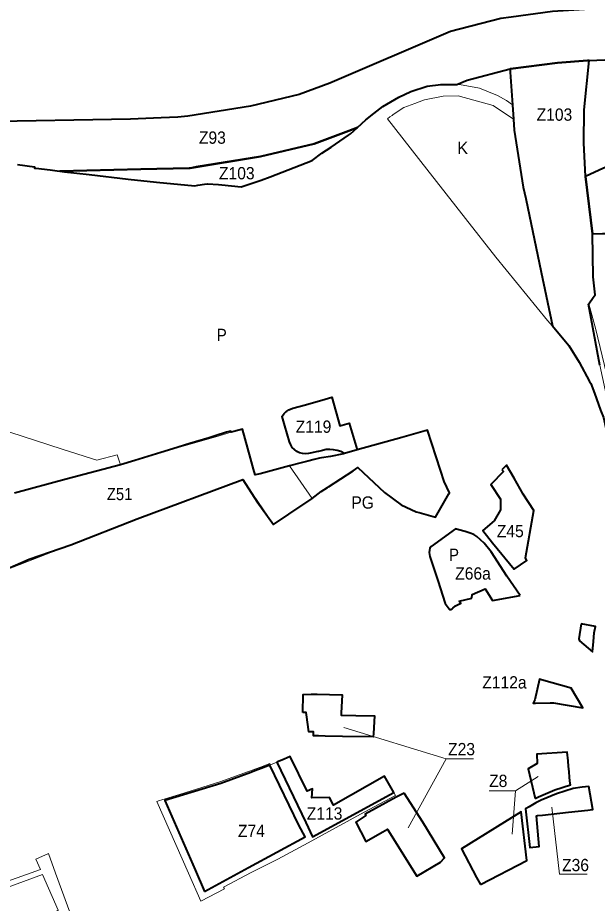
# Model space of a CAD drawing. Extents: x -650276 to -642489, y -1074311 to -1066658.
# Drawn here: x -649001 to -647871, y -1070697 to -1068970 of the extents above; entities that cross this region are included whole.
import ezdxf

# ---------------------------------------------------------------- set-up
doc = ezdxf.new("R2010")
doc.units = 0
doc.header["$LTSCALE"] = 9.6
for name, color, linetype, lineweight in [('44', 7, 'Continuous', 40), ('45', 7, 'Continuous', 40), ('46', 7, 'Continuous', 13), ('47', 7, 'Continuous', 13), ('48', 7, 'Continuous', 13), ('60', 7, 'Continuous', 35), ('63', 7, 'Continuous', 13)]:
    doc.layers.add(name, color=color, linetype=linetype, lineweight=lineweight)

msp = doc.modelspace()

# ---------------------------------------------------------------- linework, layer by layer
at = {"layer": '44'}
for points in [[(-647749.978, -1068953.416), (-647850.043, -1068951.099), (-647864.531, -1068951.823), (-647895.901, -1068953.392), (-647958.168, -1068957.73), (-648038.596, -1068968.281), (-648038.596, -1068968.281), (-648038.746, -1068968.301), (-648058.764, -1068970.927)], [(-648058.764, -1068970.927), (-648156.739, -1068996.273), (-648392.002, -1069097.554), (-648451.865, -1069119.456), (-648547.243, -1069141.81), (-648668.959, -1069161.838), (-648688.912, -1069163.603), (-648721.315, -1069164.952), (-648781.015, -1069167.44), (-649076.02, -1069172.683)], [(-647948.18, -1069057.276), (-647889.927, -1069053.218), (-647886.615, -1069053.052)], [(-647886.615, -1069053.052), (-647889.927, -1069053.218), (-647948.18, -1069057.276)], [(-647887.087, -1069527.229), (-647878.73, -1069515.45), (-647874.75, -1069509.84), (-647878.93, -1069475.09), (-647880.326, -1069390.832), (-647893.553, -1069279.021), (-647896.67, -1069213.573), (-647896.362, -1069149.171), (-647886.615, -1069053.052)], [(-647886.615, -1069053.052), (-647856.541, -1069051.548), (-647756.441, -1069053.207), (-647708.401, -1069056.275), (-647511.94, -1069076.703), (-647426.417, -1069084.624), (-647344.902, -1069091.02), (-647270.522, -1069094.255), (-647197.498, -1069094.255), (-647123.648, -1069091.043), (-647065.688, -1069087.73)], [(-648665.007, -1069262.694), (-648527.693, -1069239.938), (-648423.173, -1069215.44), (-648354.978, -1069190.492), (-648338.523, -1069183.389), (-648322.14, -1069168.56), (-648306.83, -1069156.57), (-648289.25, -1069142.79), (-648257.5, -1069124.41), (-648234.22, -1069113.6), (-648202.46, -1069103.3), (-648175.65, -1069099.64), (-648144.866, -1069099.987), (-648124.327, -1069091.181), (-648040.705, -1069069.547), (-648040.456, -1069069.483)], [(-648040.456, -1069069.483), (-648040.537, -1069075.531), (-648036.291, -1069139.458), (-648034.421, -1069167.61)], [(-648040.456, -1069069.483), (-648039.666, -1069069.279), (-647948.18, -1069057.276)], [(-647948.18, -1069057.276), (-648039.666, -1069069.279), (-648040.456, -1069069.483)], [(-648034.421, -1069167.61), (-648033, -1069189), (-648015, -1069300), (-648010.092, -1069322.087), (-647980.331, -1069465.915), (-647958.34, -1069570.699), (-647925.99, -1069608.57)], [(-648354.978, -1069190.492), (-648423.173, -1069215.44), (-648527.693, -1069239.938), (-648652.716, -1069260.657)], [(-648526.15, -1069286.21), (-648508.95, -1069280.01), (-648427.08, -1069247.75), (-648407.73, -1069233.88), (-648389.91, -1069221.86), (-648355.81, -1069198.88), (-648351.77, -1069195.88), (-648338.523, -1069183.389), (-648354.978, -1069190.492)], [(-649001.3, -1069255.92), (-648968.49, -1069260.36), (-648968.05, -1069263.06), (-648965.8, -1069262.75), (-648937.91, -1069266.51), (-648924.13, -1069268.21), (-648918.889, -1069268.875)], [(-648652.716, -1069260.657), (-648665.007, -1069262.694), (-648666.827, -1069262.738)], [(-648918.889, -1069268.875), (-648761.189, -1069265.035), (-648666.827, -1069262.738), (-648665.007, -1069262.694)], [(-648666.827, -1069262.738), (-648761.189, -1069265.035), (-648918.889, -1069268.875), (-648909.86, -1069270.02), (-648861.49, -1069275.34), (-648785.92, -1069284.2), (-648730.66, -1069290.43), (-648730.66, -1069290.43), (-648655.53, -1069297.18), (-648650.06, -1069296.39), (-648636.85, -1069294.49)], [(-648636.85, -1069294.49), (-648630.82, -1069293.63), (-648609.425, -1069295.033), (-648603.228, -1069295.53), (-648565.18, -1069299.46), (-648526.15, -1069286.21)], [(-647865.69, -1069647.32), (-647887.649, -1069528.021), (-647887.087, -1069527.229)], [(-647925.99, -1069608.57), (-647906.16, -1069641.48), (-647885.665, -1069678.788), (-647885.663, -1069678.794), (-647883.51, -1069682.71), (-647875.82, -1069701.85)], [(-647875.82, -1069701.85), (-647864.19, -1069735.12), (-647858.44, -1069749.43), (-647852.63, -1069775.7), (-647850.66, -1069785.74), (-647849.165, -1069793.367), (-647843.74, -1069817.63), (-647841.402, -1069792.351)]]:
    msp.add_lwpolyline(points, dxfattribs=at)
msp.add_lwpolyline([(-647860.52, -1069390.72), (-647848.24, -1069390.65), (-647845.25, -1069390.07), (-647843.41, -1069389.23), (-647841.81, -1069387.99), (-647840.42, -1069386.51), (-647839.4, -1069384.73), (-647838.79, -1069382.86), (-647836.2, -1069362.68), (-647832.29, -1069338.58), (-647832.29, -1069338.58), (-647831.19, -1069320.69), (-647830.23, -1069305.38), (-647826.928, -1069253.199), (-647848.17, -1069259.21), (-647858.37, -1069263.03), (-647893.553, -1069279.017), (-647880.326, -1069390.832)], close=True, dxfattribs=at)
msp.add_arc((-648354.978, -1069190.492), 0.000000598, 264.13978, 298.69712, dxfattribs=at)
at = {"layer": '45'}
for points in [[(-648338.933, -1069812.492), (-648363.563, -1069819.352), (-648371.093, -1069815.602), (-648377.983, -1069813.332), (-648385.093, -1069811.952), (-648392.333, -1069811.482), (-648399.563, -1069811.922), (-648406.723, -1069813.272), (-648414.54, -1069815.288), (-648415.873, -1069815.632), (-648430.764, -1069818.704), (-648433.853, -1069819.342), (-648439.773, -1069820.012), (-648445.683, -1069819.552), (-648451.413, -1069818.022), (-648456.763, -1069815.432), (-648461.523, -1069811.902), (-648465.553, -1069807.532), (-648468.703, -1069802.482), (-648470.853, -1069796.942), (-648480.15, -1069765.358), (-648485.323, -1069747.432), (-648485.023, -1069746.592), (-648483.157, -1069743.818), (-648481.673, -1069741.612), (-648477.273, -1069737.482), (-648475.905, -1069736.566), (-648472.283, -1069734.142), (-648464.333, -1069730.932), (-648439.683, -1069724.232), (-648401.171, -1069713.196), (-648388.514, -1069709.779), (-648372.522, -1069765.283), (-648354.898, -1069760.328)], [(-648057.11, -1069851.12), (-648053.61, -1069854.64), (-648078.54, -1069880.01), (-648059.32, -1069908.27), (-648059.5, -1069929.52), (-648071.58, -1069950.39), (-648093.67, -1069969.42), (-648074.96, -1069993.46), (-648032.85, -1070044.73), (-648008.18, -1070028.25), (-648010.44, -1070023.66), (-648010.94, -1070022.65), (-647994.71, -1069930.53), (-648015.11, -1069898.98), (-648032.94, -1069867.46), (-648048.08, -1069841.95)], [(-648057.11, -1069851.12), (-648053.61, -1069854.64), (-648078.54, -1069880.01), (-648059.32, -1069908.27), (-648059.5, -1069929.52), (-648071.58, -1069950.39), (-648093.67, -1069969.42), (-648074.96, -1069993.46), (-648032.85, -1070044.73), (-648008.18, -1070028.25), (-648010.44, -1070023.66), (-648010.94, -1070022.65), (-647994.71, -1069930.53), (-648015.11, -1069898.98), (-648032.94, -1069867.46), (-648048.08, -1069841.95)], [(-647902.17, -1070151.64), (-647906.6, -1070180.65), (-647905.17, -1070184.5), (-647879.81, -1070206.08), (-647878.18, -1070186.33), (-647876.74, -1070168.88), (-647873.97, -1070156.58)], [(-647902.17, -1070151.64), (-647906.6, -1070180.65), (-647905.17, -1070184.5), (-647879.81, -1070206.08), (-647878.18, -1070186.33), (-647876.74, -1070168.88), (-647873.97, -1070156.58)], [(-647962.82, -1070305.9), (-647956.36, -1070305.77), (-647898.82, -1070315.51), (-647921.51, -1070276.76), (-647979.24, -1070260.71), (-647983.6, -1070259.5), (-647992.71, -1070300.01), (-647995.46, -1070306.55), (-647991.12, -1070306.46)], [(-648444.85, -1070324.47), (-648444.15, -1070289.16), (-648428.98, -1070288.92), (-648416.93, -1070288.85), (-648392.94, -1070289.25), (-648368.25, -1070289.71), (-648370.07, -1070325.94), (-648370.07, -1070329.902), (-648341.46, -1070330.48), (-648305.47, -1070331.23), (-648307.13, -1070365.57), (-648307.67, -1070371.78), (-648367.67, -1070371.16), (-648401.35, -1070370.5), (-648414.75, -1070370.24), (-648424.05, -1070370), (-648424.31, -1070362.21), (-648433.46, -1070361.94), (-648437.65, -1070328.8), (-648438.296, -1070324.598)], [(-648444.85, -1070324.47), (-648444.15, -1070289.16), (-648428.98, -1070288.92), (-648416.93, -1070288.85), (-648392.94, -1070289.25), (-648368.25, -1070289.71), (-648370.07, -1070325.94), (-648370.07, -1070329.902), (-648341.46, -1070330.48), (-648305.47, -1070331.23), (-648307.13, -1070365.57), (-648307.67, -1070371.78), (-648367.67, -1070371.16), (-648401.35, -1070370.5), (-648414.75, -1070370.24), (-648424.05, -1070370), (-648424.31, -1070362.21), (-648433.46, -1070361.94), (-648437.65, -1070328.8), (-648438.296, -1070324.598)], [(-648495.666, -1070421.476), (-648439.409, -1070538.729), (-648425.835, -1070567.021), (-648267.801, -1070480.55), (-648285.75, -1070448.49), (-648385.085, -1070505.351), (-648393.14, -1070490.07), (-648427.41, -1070491.08), (-648426.05, -1070473.34), (-648436.22, -1070478.01), (-648469.77, -1070410.47), (-648481.18, -1070415.62)], [(-648495.666, -1070421.476), (-648439.409, -1070538.729), (-648425.835, -1070567.021), (-648267.801, -1070480.55), (-648285.75, -1070448.49), (-648385.085, -1070505.351), (-648393.14, -1070490.07), (-648427.41, -1070491.08), (-648426.05, -1070473.34), (-648436.22, -1070478.01), (-648469.77, -1070410.47), (-648481.18, -1070415.62)], [(-647991.539, -1070492.016), (-647985.19, -1070488.804), (-647953.251, -1070475.276), (-647923.247, -1070465.749), (-647923.53, -1070462.75), (-647924.63, -1070451.09), (-647925.5, -1070439.63), (-647926.53, -1070429.76), (-647927.67, -1070418.74), (-647929.24, -1070401.97), (-647988.86, -1070405.95), (-647988.11, -1070423.93), (-648005.668, -1070434.145)], [(-648636.757, -1070673.431), (-648550.72, -1070626.869), (-648440.531, -1070567.236), (-648452.97, -1070544.21), (-648509.227, -1070426.957), (-648526.28, -1070433.85), (-648538.611, -1070438.388), (-648546.377, -1070441.246), (-648604.92, -1070462.79), (-648714.161, -1070496.376), (-648655.178, -1070631.294)], [(-647950.48, -1070482.79), (-647980.4, -1070495.463), (-647990.295, -1070500.352), (-648003.85, -1070508.218), (-648010.831, -1070512.588), (-648002, -1070588), (-647984.03, -1070585.46), (-647989.5, -1070525.73), (-647987.436, -1070525.508), (-647977.41, -1070524.43), (-647927.14, -1070519), (-647889.27, -1070514.92), (-647879.89, -1070513.91), (-647879.16, -1070513.83), (-647887.08, -1070468.54), (-647899.87, -1070470.04), (-647917.98, -1070472.47)], [(-648247.67, -1070481.57), (-648262.69, -1070489.67), (-648323.59, -1070522.48), (-648322.18, -1070525.44), (-648341.41, -1070538.42), (-648322.16, -1070575.76), (-648289.22, -1070557.15), (-648279.736, -1070551.783), (-648278.89, -1070553.14), (-648222.58, -1070643.48), (-648176.54, -1070616.09), (-648168.575, -1070607.847), (-648211, -1070538)], [(-648247.67, -1070481.57), (-648262.69, -1070489.67), (-648323.59, -1070522.48), (-648322.18, -1070525.44), (-648341.41, -1070538.42), (-648322.16, -1070575.76), (-648289.22, -1070557.15), (-648279.736, -1070551.783), (-648278.89, -1070553.14), (-648222.58, -1070643.48), (-648176.54, -1070616.09), (-648168.575, -1070607.847), (-648211, -1070538)], [(-648098.637, -1070659.682), (-648007.838, -1070612.851), (-648019, -1070518), (-648135.47, -1070590.61), (-648105.98, -1070645.91)]]:
    msp.add_lwpolyline(points, close=True, dxfattribs=at)
for points in [[(-649048.918, -1070055.852), (-648978.654, -1070025.669), (-648897.735, -1069997.25), (-648767.83, -1069946.87), (-648562.242, -1069870.301), (-648533.79, -1069913.49), (-648502.048, -1069957.969), (-648472.6, -1069937.81), (-648426.82, -1069906.88), (-648409.44, -1069893.25), (-648396.87, -1069885.43), (-648395.03, -1069884.22), (-648347.06, -1069853), (-648337.48, -1069846.531), (-648285.62, -1069895.71), (-648253.13, -1069919.7), (-648223.99, -1069932.96), (-648218.245, -1069934.595), (-648186.268, -1069943.697), (-648160.04, -1069897.73), (-648159.1, -1069896.39), (-648169.15, -1069873.81), (-648176.78, -1069851.74), (-648201.83, -1069773.86), (-648247.27, -1069786.64), (-648251.94, -1069787.95), (-648339.05, -1069812.45), (-648363.68, -1069819.31), (-648365.81, -1069819.9), (-648391.08, -1069825.45), (-648408.45, -1069827.83), (-648412.74, -1069828.72), (-648422.75, -1069830.78), (-648435.53, -1069834.44), (-648447.98, -1069837.44), (-648470.79, -1069843.51), (-648528.11, -1069858.73), (-648537.86, -1069861.22), (-648541.06, -1069849.78), (-648546.97, -1069828.68), (-648562.87, -1069771.85), (-648579.63, -1069776.66), (-648584.65, -1069778.1), (-648586.09, -1069775.75), (-648593.59, -1069778.06), (-648615.88, -1069784.93), (-648627.99, -1069788.67), (-648665.05, -1069799.99), (-648698.31, -1069810.16), (-648722.24, -1069817.54), (-648772.48, -1069832.83), (-648800.85, -1069841.52), (-648906.547, -1069869.711), (-649007.37, -1069896.602)], [(-648128.48, -1069971.7), (-648140.96, -1069968.01), (-648147.46, -1069966.19), (-648194.84, -1070000.49)], [(-648111.44, -1069977.32), (-648118.75, -1069974.53), (-648128.48, -1069971.7)], [(-648021.35, -1070096.14), (-648046.83, -1070058.62), (-648077.68, -1070011.06), (-648091.06, -1069994.07), (-648105.79, -1069981.56), (-648111.44, -1069977.32)], [(-648194.84, -1070000.49), (-648197.19, -1070003.94), (-648198.17, -1070008.05), (-648198.48, -1070012.3), (-648198.22, -1070016.4), (-648197.23, -1070020.37), (-648182.01, -1070067.11)], [(-648182.01, -1070067.11), (-648167.48, -1070111.75), (-648159.89, -1070122.49), (-648159.02, -1070123.71), (-648156.07, -1070123.54)], [(-648115.11, -1070101.26), (-648114.7, -1070094.68), (-648089.22, -1070083.27), (-648074.76, -1070106.17), (-648021.35, -1070096.14)], [(-648152.35, -1070121.05), (-648147.02, -1070116.35), (-648139.45, -1070112.79), (-648136.61, -1070111.97), (-648139.91, -1070107.48), (-648115.11, -1070101.26)], [(-648156.07, -1070123.54), (-648153.85, -1070122.38), (-648152.35, -1070121.05)]]:
    msp.add_lwpolyline(points, dxfattribs=at)
at = {"layer": '46'}
for p, q in [((-648165.109, -1070414.543), (-648239.52, -1070549.62)), ((-648165.109, -1070414.543), (-648239.52, -1070549.62)), ((-648030.462, -1070477.049), (-648036.992, -1070561.483)), ((-647944.293, -1070639.492), (-647959.279, -1070509.201)), ((-647890.215, -1070639.492), (-647944.293, -1070639.492)), ((-647890.215, -1070639.492), (-647904.43, -1070639.492))]:
    msp.add_line(p, q, dxfattribs=at)
for points in [[(-648112.329, -1070414.543), (-648165.109, -1070414.543), (-648364.98, -1070353.932)], [(-648112.329, -1070414.543), (-648165.109, -1070414.543), (-648364.98, -1070353.932)], [(-648081.63, -1070477.049), (-648030.462, -1070477.049), (-647985.902, -1070448.995)]]:
    msp.add_lwpolyline(points, dxfattribs=at)
at = {"layer": '47'}
for points in [[(-648036.291, -1069139.458), (-648040.537, -1069075.531), (-648040.5, -1069072.79), (-648040.705, -1069069.548), (-648124.327, -1069091.181), (-648144.866, -1069099.987)], [(-648144.866, -1069099.987), (-648139.27, -1069100.05), (-648100.37, -1069107.1), (-648100.37, -1069107.1), (-648065.16, -1069121.12)], [(-648065.16, -1069121.12), (-648048.06, -1069130.81), (-648036.291, -1069139.458)]]:
    msp.add_lwpolyline(points, dxfattribs=at)
for points in [[(-648127.77, -1069361.38), (-648068.71, -1069436.57), (-647967.53, -1069559.94), (-647958.214, -1069571.3), (-647980.331, -1069465.915), (-648010.092, -1069322.087), (-648015, -1069300), (-648033, -1069189), (-648034.421, -1069167.61), (-648073.66, -1069140.86), (-648141.92, -1069121.66), (-648171.14, -1069122.83), (-648207.77, -1069129.95), (-648209.89, -1069130.36), (-648226.51, -1069136.57), (-648248.14, -1069144.65), (-648268.87, -1069158.61), (-648270.92, -1069159.99), (-648275.19, -1069162.87), (-648280.1, -1069166.97), (-648203.01, -1069264.73)], [(-647845.086, -1069748.753), (-647842.438, -1069760.647), (-647844.371, -1069761.991), (-647843.337, -1069769.013), (-647822.54, -1069759.29), (-647830, -1069744.7), (-647835.76, -1069730.01), (-647845.85, -1069691.2), (-647852.44, -1069664.03), (-647873.43, -1069577.87), (-647887.087, -1069527.229), (-647865.69, -1069647.32), (-647855.158, -1069695.232), (-647846.484, -1069736.663)], [(-649014.888, -1070782.994), (-648966.35, -1070764.7), (-648908.94, -1070740.19), (-648892.215, -1070733.293), (-648927.2, -1070637.98), (-648941.064, -1070599.735), (-648965.569, -1070610.382), (-648956.687, -1070630.825), (-649050.081, -1070663.981), (-649047.11, -1070674.743), (-648952.455, -1070640.564), (-648922.196, -1070710.207), (-648924.668, -1070712.022), (-648943.837, -1070720.104), (-649025.129, -1070754.377)]]:
    msp.add_lwpolyline(points, close=True, dxfattribs=at)
at = {"layer": '63'}
for points in [[(-648502.048, -1069957.969), (-648472.6, -1069937.81), (-648438.08, -1069914.49), (-648426.82, -1069906.88), (-648470.79, -1069843.51), (-648537.86, -1069861.22), (-648541.06, -1069849.78), (-648546.97, -1069828.68), (-648562.87, -1069771.85), (-648584.65, -1069778.1), (-648614.79, -1069786.74), (-648722.24, -1069817.54), (-648772.48, -1069832.83), (-648800.85, -1069841.52), (-648806.946, -1069821.79), (-648846.924, -1069832.58), (-648856.932, -1069829.35), (-648914.48, -1069810.75), (-649069.4, -1069760.67)], [(-649239.635, -1069943.094), (-649202.375, -1070030.469), (-649085.737, -1070078.201), (-649048.918, -1070055.852), (-648767.83, -1069946.87), (-648562.242, -1069870.301), (-648502.048, -1069957.969)], [(-648643.953, -1070692.685), (-648643.953, -1070692.685), (-648597.74, -1070668.62), (-648599.66, -1070665.32), (-648545.76, -1070636.22), (-648494.04, -1070610.73), (-648434.43, -1070578.53), (-648325.21, -1070518.84), (-648264.56, -1070486.34), (-648285.75, -1070448.49), (-648385.085, -1070505.351), (-648393.14, -1070490.07), (-648427.41, -1070491.08), (-648426.05, -1070473.34), (-648436.22, -1070478.01), (-648469.77, -1070410.47), (-648481.18, -1070415.62), (-648508.278, -1070426.53), (-648509.26, -1070424.06), (-648527.6, -1070431.05), (-648606.55, -1070459.91), (-648685.48, -1070484.2), (-648719.84, -1070494.77), (-648724.84, -1070496.31), (-648729.551, -1070497.758)], [(-648729.551, -1070497.758), (-648668.207, -1070637.453), (-648668.207, -1070637.453), (-648643.953, -1070692.685)]]:
    msp.add_lwpolyline(points, dxfattribs=at)

# ---------------------------------------------------------------- texts
at = {"layer": '44', "width": 0.95}
for s, p in [('Z103', (-647989.032, -1069170.515)), ('Z103', (-647989.032, -1069170.515)), ('Z93', (-648647.673, -1069215.426)), ('Z93', (-648647.673, -1069215.426)), ('Z103', (-648608.542, -1069284.81)), ('Z103', (-648608.542, -1069284.81))]:
    msp.add_text(s, height=24, dxfattribs=at).set_placement(p)
at = {"layer": '46'}
for s, width, p in [('Z119', 0.95, (-648458.914, -1069779.092)), ('Z51', 0.9, (-648827.214, -1069910.388)), ('Z45', 0.95, (-648066.663, -1069982.614)), ('Z45', 0.95, (-648066.663, -1069982.614)), ('Z66a', 0.95, (-648147.889, -1070065.308)), ('Z112a', 0.95, (-648094.972, -1070277.658)), ('Z23', 0.95, (-648161.708, -1070407.912)), ('Z23', 0.95, (-648161.708, -1070407.912)), ('Z8', 0.95, (-648081.661, -1070469.822)), ('Z113', 0.95, (-648437.324, -1070533.384)), ('Z113', 0.95, (-648437.324, -1070533.384)), ('Z74', 0.95, (-648571.565, -1070567.472)), ('Z36', 0.95, (-647939.415, -1070633.92)), ('Z36', 0.95, (-647939.415, -1070633.92))]:
    msp.add_text(s, height=24, dxfattribs=dict(at, width=width)).set_placement(p)
at = {"layer": '48'}
msp.add_text('K', height=24, dxfattribs=at).set_placement((-648144.004, -1069235.577))
msp.add_text('K', height=24, dxfattribs=at).set_placement((-648144.004, -1069235.577))
at = {"layer": '60'}
for s, width, p in [('P', 0.9, (-648612.658, -1069600.244)), ('PG', 0.95, (-648350.408, -1069926.995)), ('P', 0.9, (-648159.699, -1070028.97))]:
    msp.add_text(s, height=24, dxfattribs=dict(at, width=width)).set_placement(p)

doc.saveas('drawing.dxf')
